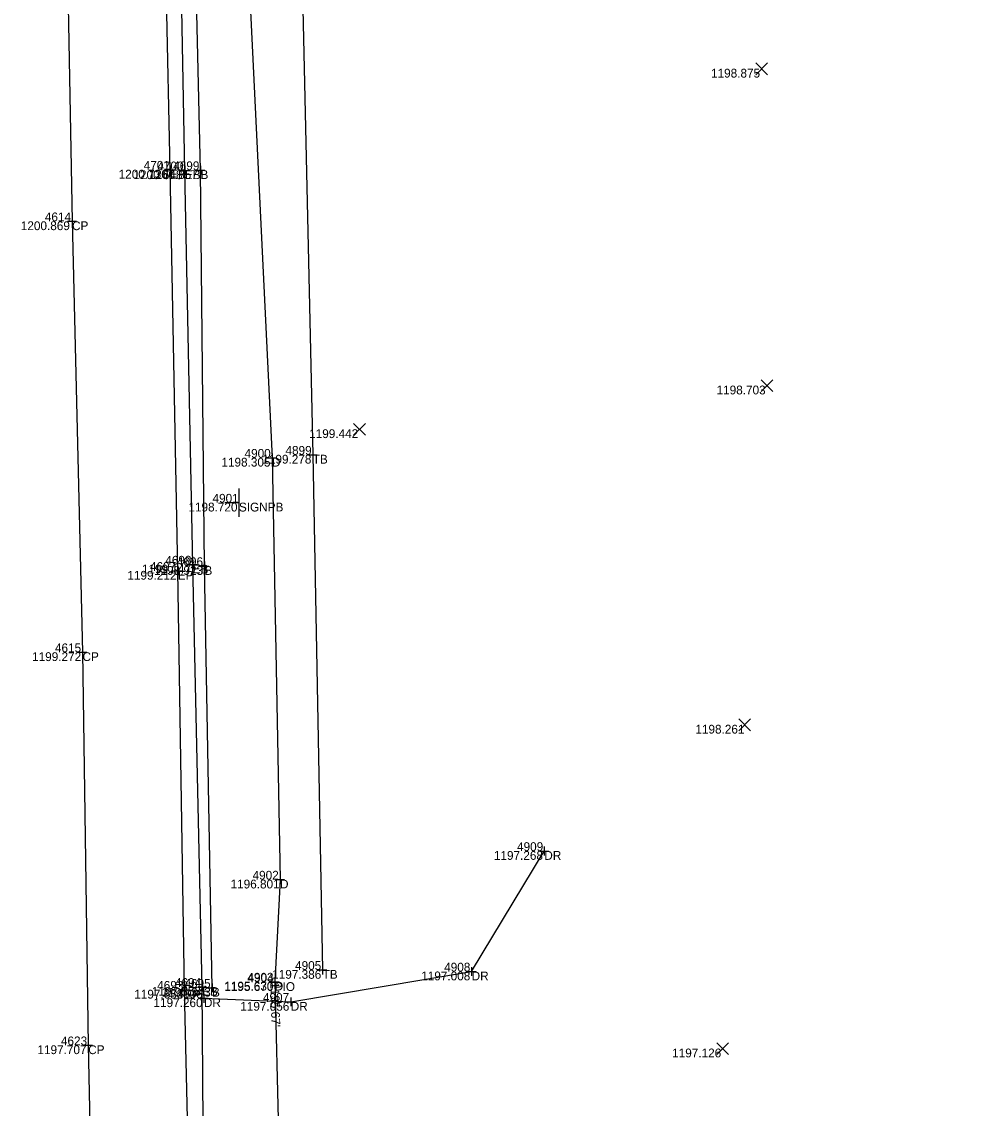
# Model space of a CAD drawing. Extents: x 2044996 to 2050343, y 455232 to 458054.
# Drawn here: x 2047636.8 to 2047743.9, y 456392.6 to 456516 of the extents above; entities that cross this region are included whole.
import ezdxf

# ---------------------------------------------------------------- set-up
doc = ezdxf.new("R2010")
doc.units = 0
for name, color, linetype in [('DR_X_Ditch', 7, 'Continuous'), ('DR_X_Elev_Flow', 7, 'Continuous'), ('DR_X_Storm_Sewer', 7, 'Continuous'), ('DT_X_Contour_Minor', 7, 'Continuous'), ('DT_X_Contour_Text', 7, 'Continuous'), ('DT_X_Spot_Elev', 7, 'Continuous'), ('DT_X_Triangles', 7, 'Continuous'), ('DT_X_Void', 7, 'Continuous'), ('PV_X_COP', 7, 'Continuous'), ('PV_X_Driveway', 7, 'Continuous'), ('PV_X_EOP', 7, 'Continuous'), ('PV_X_Shoulder_Aggregate', 7, 'Continuous'), ('SC_Scratch1', 7, 'Continuous'), ('SN_X_Public', 7, 'Continuous'), ('SV_X_Break_Lines', 7, 'Continuous'), ('SV_X_Top_of_Bank', 7, 'Continuous')]:
    doc.layers.add(name, color=color, linetype=linetype)

msp = doc.modelspace()

# ---------------------------------------------------------------- linework, layer by layer
at = {"layer": 'DR_X_Ditch'}
msp.add_lwpolyline([(2047944.96, 456861.76), (2047899.25, 456878.16), (2047861.64, 456891.96), (2047815.35, 456909.09), (2047774.86, 456921.86), (2047729.93, 456938.25), (2047691.42, 456950.76), (2047669.22, 456956.37), (2047658.75, 456950.98), (2047651.4, 456909.49), (2047651.98, 456861.4), (2047653.43, 456816.89), (2047656.94, 456761.43), (2047657.83, 456718.94), (2047659.36, 456677.43), (2047660.77, 456628.12), (2047661.37, 456577.1), (2047662.68, 456519.59), (2047665.25, 456466.46), (2047666.16, 456418.54), (2047665.56, 456406.95)], dxfattribs=at)
at = {"layer": 'DR_X_Elev_Flow'}
for p, q in [((2047665.06, 456406.89), (2047666.06, 456406.89)), ((2047665.56, 456407.39), (2047665.56, 456406.39)), ((2047665.56, 456406.89), (2047665.56, 456406.89))]:
    msp.add_line(p, q, dxfattribs=at)
at = {"layer": 'DR_X_Storm_Sewer'}
msp.add_line((2047665.56, 456406.89), (2047667.64, 456327.27), dxfattribs=at)
at = {"layer": 'DT_X_Spot_Elev'}
for p, q in [((2047720.23, 456509.98), (2047721.56, 456511.32)), ((2047720.23, 456511.32), (2047721.56, 456509.98)), ((2047720.83, 456473.99), (2047722.17, 456475.33)), ((2047720.83, 456475.33), (2047722.17, 456473.99)), ((2047674.53, 456469.03), (2047675.86, 456470.37)), ((2047674.53, 456470.37), (2047675.86, 456469.03)), ((2047718.32, 456435.46), (2047719.65, 456436.79)), ((2047718.32, 456436.79), (2047719.65, 456435.46)), ((2047715.81, 456398.69), (2047717.14, 456400.02)), ((2047715.81, 456400.02), (2047717.14, 456398.69))]:
    msp.add_line(p, q, dxfattribs=at)
at = {"layer": 'DT_X_Void'}
for p, q in [((2047653.66, 456499.68), (2047653.66, 456498.68)), ((2047655.34, 456499.61), (2047655.34, 456498.61)), ((2047657.12, 456499.63), (2047657.12, 456498.63)), ((2047653.16, 456499.18), (2047654.16, 456499.18)), ((2047653.66, 456499.18), (2047653.66, 456499.18)), ((2047654.84, 456499.11), (2047655.84, 456499.11)), ((2047655.34, 456499.11), (2047655.34, 456499.11)), ((2047656.62, 456499.13), (2047657.62, 456499.13)), ((2047657.12, 456499.13), (2047657.12, 456499.13)), ((2047642.02, 456493.32), (2047643.02, 456493.32)), ((2047642.52, 456493.82), (2047642.52, 456492.82)), ((2047642.52, 456493.32), (2047642.52, 456493.32)), ((2047669.88, 456467.3), (2047669.88, 456466.3)), ((2047664.75, 456466.46), (2047665.75, 456466.46)), ((2047665.25, 456466.96), (2047665.25, 456465.96)), ((2047665.25, 456466.46), (2047665.25, 456466.46)), ((2047669.38, 456466.8), (2047670.38, 456466.8)), ((2047669.88, 456466.8), (2047669.88, 456466.8)), ((2047654.54, 456454.11), (2047654.54, 456453.11)), ((2047655.74, 456454.32), (2047656.74, 456454.32)), ((2047656.24, 456454.82), (2047656.24, 456453.82)), ((2047656.24, 456454.32), (2047656.24, 456454.32)), ((2047657.07, 456454.16), (2047658.07, 456454.16)), ((2047657.57, 456454.66), (2047657.57, 456453.66)), ((2047657.57, 456454.16), (2047657.57, 456454.16)), ((2047654.04, 456453.61), (2047655.04, 456453.61)), ((2047654.54, 456453.61), (2047654.54, 456453.61)), ((2047643.21, 456444.37), (2047644.21, 456444.37)), ((2047643.71, 456444.87), (2047643.71, 456443.87)), ((2047643.71, 456444.37), (2047643.71, 456444.37)), ((2047695.7, 456421.79), (2047696.7, 456421.79)), ((2047696.2, 456422.29), (2047696.2, 456421.29)), ((2047696.2, 456421.79), (2047696.2, 456421.79)), ((2047665.66, 456418.54), (2047666.66, 456418.54)), ((2047666.16, 456419.04), (2047666.16, 456418.04)), ((2047666.16, 456418.54), (2047666.16, 456418.54)), ((2047670.5, 456408.28), (2047671.5, 456408.28)), ((2047671, 456408.78), (2047671, 456407.78)), ((2047671, 456408.28), (2047671, 456408.28)), ((2047687.44, 456408.1), (2047688.44, 456408.1)), ((2047687.94, 456408.6), (2047687.94, 456407.6)), ((2047687.94, 456408.1), (2047687.94, 456408.1)), ((2047657.31, 456406.85), (2047657.31, 456405.85)), ((2047665.06, 456406.95), (2047666.06, 456406.95)), ((2047665.56, 456407.45), (2047665.56, 456406.45)), ((2047665.56, 456406.95), (2047665.56, 456406.95)), ((2047654.81, 456406.03), (2047655.81, 456406.03)), ((2047655.31, 456406.53), (2047655.31, 456405.53)), ((2047655.31, 456406.03), (2047655.31, 456406.03)), ((2047656.81, 456406.35), (2047657.81, 456406.35)), ((2047657.31, 456406.35), (2047657.31, 456406.35)), ((2047657.93, 456406.25), (2047658.93, 456406.25)), ((2047658.43, 456406.75), (2047658.43, 456405.75)), ((2047658.43, 456406.25), (2047658.43, 456406.25)), ((2047657.01, 456405.06), (2047658.01, 456405.06)), ((2047657.51, 456405.56), (2047657.51, 456404.56)), ((2047657.51, 456405.06), (2047657.51, 456405.06)), ((2047666.88, 456404.65), (2047667.88, 456404.65)), ((2047667.38, 456405.15), (2047667.38, 456404.15)), ((2047667.38, 456404.65), (2047667.38, 456404.65)), ((2047643.86, 456399.72), (2047644.86, 456399.72)), ((2047644.36, 456400.22), (2047644.36, 456399.22)), ((2047644.36, 456399.72), (2047644.36, 456399.72))]:
    msp.add_line(p, q, dxfattribs=at)
at = {"layer": 'PV_X_COP'}
msp.add_lwpolyline([(2047638.65, 456684.97), (2047639.72, 456638.63), (2047640.67, 456589.24), (2047641.66, 456540.18), (2047642.52, 456493.32), (2047643.71, 456444.37), (2047644.36, 456399.72), (2047645.21, 456358.38), (2047646.69, 456312.13), (2047647.16, 456279.14), (2047647.64, 456246.5), (2047648.01, 456224.8), (2047648.98, 456176.78), (2047649.64, 456128.98), (2047650.62, 456077.99), (2047651.48, 456030.79), (2047652.41, 455980.92), (2047652.55, 455976.29)], dxfattribs=at)
at = {"layer": 'PV_X_Driveway'}
msp.add_lwpolyline([(2047657.51, 456405.06), (2047667.38, 456404.65), (2047687.94, 456408.1), (2047696.2, 456421.79)], dxfattribs=at)
at = {"layer": 'PV_X_EOP'}
for p, q in [((2047653.66, 456499.18), (2047652.74, 456545.59)), ((2047654.54, 456453.61), (2047653.66, 456499.18)), ((2047655.31, 456406.03), (2047654.54, 456453.61)), ((2047656.16, 456369.54), (2047655.31, 456406.03))]:
    msp.add_line(p, q, dxfattribs=at)
at = {"layer": 'PV_X_Shoulder_Aggregate'}
msp.add_lwpolyline([(2047664.76, 455980.11), (2047663.65, 456028.13), (2047662.66, 456078.84), (2047661.94, 456126.71), (2047661.18, 456172.4), (2047660.15, 456223.29), (2047659.21, 456276.46), (2047658.4, 456325.53), (2047657.58, 456370.17), (2047657.31, 456406.35), (2047656.24, 456454.32), (2047655.34, 456499.11), (2047654.47, 456545.86), (2047653.3, 456590.72), (2047651.94, 456638.93), (2047650.86, 456688.18)], dxfattribs=at)
at = {"layer": 'SN_X_Public'}
for p, q in [((2047661.49, 456462.96), (2047661.49, 456459.76)), ((2047661.49, 456461.36), (2047659.89, 456461.36))]:
    msp.add_line(p, q, dxfattribs=at)
at = {"layer": 'SV_X_Break_Lines'}
msp.add_lwpolyline([(2047658.43, 456406.25), (2047657.57, 456454.16), (2047657.12, 456499.13), (2047656.02, 456546.18), (2047654.76, 456590.52), (2047653.67, 456638.77), (2047652.84, 456687.95), (2047651.32, 456732.84), (2047649.31, 456778.74), (2047648.48, 456826.81), (2047647.99, 456872.14), (2047647.65, 456917.64), (2047648.11, 456940.22), (2047652.79, 456955.84)], dxfattribs=at)
at = {"layer": 'SV_X_Top_of_Bank'}
msp.add_lwpolyline([(2047942.14, 456857.99), (2047898.01, 456872.36), (2047859.06, 456885.19), (2047815.47, 456901.27), (2047771.85, 456916.42), (2047729.97, 456932.49), (2047688.22, 456947.3), (2047669.99, 456955.17), (2047661.07, 456948.62), (2047656.72, 456911.9), (2047659.76, 456864.17), (2047662.28, 456815.7), (2047662.72, 456763.39), (2047662.48, 456719.38), (2047665.2, 456677.14), (2047665.7, 456629.87), (2047667.28, 456578.15), (2047668.69, 456520.88), (2047669.88, 456466.8), (2047671, 456408.28)], dxfattribs=at)

# ---------------------------------------------------------------- texts
at = {"layer": 'DT_X_Contour_Minor'}
for s, p in [('1198.875', (2047715.15, 456509.65)), ('1200.736', (2047647.82, 456498.18)), ('1200.648', (2047649.5, 456498.11)), ('1200.357', (2047651.24, 456498.13)), ('1200.869', (2047636.7, 456492.32)), ('1198.703', (2047715.78, 456473.66)), ('1199.442', (2047669.47, 456468.7)), ('1198.305', (2047659.5, 456465.46)), ('1199.278', (2047664.15, 456465.8)), ('1198.720', (2047655.75, 456460.36)), ('1199.147', (2047650.46, 456453.32)), ('1198.923', (2047651.84, 456453.16)), ('1199.212', (2047648.81, 456452.61)), ('1199.272', (2047637.98, 456443.37)), ('1198.261', (2047713.37, 456435.13)), ('1197.268', (2047690.47, 456420.79)), ('1196.801', (2047660.54, 456417.54)), ('1197.386', (2047665.27, 456407.28)), ('1197.008', (2047682.21, 456407.1)), ('1195.630', (2047659.83, 456405.95)), ('1195.670', (2047659.83, 456405.89)), ('1197.653', (2047649.59, 456405.03)), ('1197.553', (2047651.59, 456405.35)), ('1197.343', (2047652.71, 456405.25)), ('1197.260', (2047651.78, 456404.06)), ('1197.056', (2047661.64, 456403.65)), ('1197.707', (2047638.59, 456398.72)), ('1197.126', (2047710.73, 456398.35))]:
    msp.add_text(s, height=1, dxfattribs=at).set_placement(p)
at = {"layer": 'DT_X_Contour_Text'}
for s, p in [('EP', (2047653.66, 456498.18)), ('EB', (2047655.34, 456498.11)), ('B', (2047657.12, 456498.13)), ('CP', (2047642.52, 456492.32)), ('D', (2047665.25, 456465.46)), ('TB', (2047669.88, 456465.8)), ('SIGNPB', (2047661.49, 456460.36)), ('EB', (2047656.24, 456453.32)), ('B', (2047657.57, 456453.16)), ('EP', (2047654.54, 456452.61)), ('CP', (2047643.71, 456443.37)), ('DR', (2047696.2, 456420.79)), ('D', (2047666.16, 456417.54)), ('TB', (2047671, 456407.28)), ('DR', (2047687.94, 456407.1)), ('D', (2047665.56, 456405.95)), ('PIO', (2047665.56, 456405.89)), ('EP', (2047655.31, 456405.03)), ('EB', (2047657.31, 456405.35)), ('B', (2047658.43, 456405.25)), ('DR', (2047657.51, 456404.06)), ('DR', (2047667.38, 456403.65)), ('CP', (2047644.36, 456398.72))]:
    msp.add_text(s, height=1, dxfattribs=at).set_placement(p)
at = {"layer": 'DT_X_Triangles'}
for s, p in [('4701', (2047650.67, 456499.18)), ('4700', (2047652.22, 456499.11)), ('4699', (2047654.02, 456499.13)), ('4614', (2047639.43, 456493.32)), ('4900', (2047662.13, 456466.46)), ('4899', (2047666.78, 456466.8)), ('4901', (2047658.49, 456461.36)), ('4698', (2047653.12, 456454.32)), ('4696', (2047654.44, 456454.16)), ('4697', (2047651.38, 456453.61)), ('4615', (2047640.58, 456444.37)), ('4909', (2047693.1, 456421.79)), ('4902', (2047663.04, 456418.54)), ('4905', (2047667.87, 456408.28)), ('4908', (2047684.82, 456408.1)), ('4693', (2047652.2, 456406.03)), ('4694', (2047654.22, 456406.35)), ('4695', (2047655.3, 456406.25)), ('4903', (2047662.45, 456406.95)), ('4904', (2047662.47, 456406.89)), ('4906', (2047654.39, 456405.06)), ('4907', (2047664.22, 456404.65)), ('4623', (2047641.26, 456399.72))]:
    msp.add_text(s, height=1, dxfattribs=at).set_placement(p)
at = {"layer": 'SC_Scratch1'}
msp.add_text("1195.67'", height=1, rotation=271.5003, dxfattribs=at).set_placement((2047665.06, 456406.88))

doc.saveas('drawing.dxf')
